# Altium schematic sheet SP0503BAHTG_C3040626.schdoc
size 127 x 101 mm
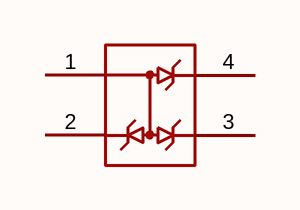
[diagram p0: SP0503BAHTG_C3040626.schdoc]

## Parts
D?  sp0503bahtg_c3040626  [SOT-143-4_L2.9-W1.3-P1.92-LS2.4-BL]  (value not drawn)

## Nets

Not connected (* = marked no-connect by the designer): D? 1 2 3 4

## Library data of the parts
D? = sp0503bahtg_c3040626: 极性:单向;反向截止电压(Vrwm):5.5V;钳位电压:14V;峰值脉冲电流(Ipp):10A@8/20us;峰值脉冲功率(Ppp):150W@8/20us;击穿电压(VBR):6V;; Manufacturer: TECH PUBLIC(台舟); AddInBom: yes; ModelId: 2837e3608ba24a5fbaabe401bacde791; ModelTransform: 114.173,93.3069,0,0,0,0,-0.003,0,0; Polarity: 单向; Reverse Stand-Off Voltage (Vrwm): 5.5V; Clamping Voltage: 14V; Voltage - Breakdown: 6V; Reverse Leakage Current (Ir): 80nA; Number of Channels: 三路; level of protection: IEC 61000-4-2；IEC 61000-4-4；IEC 61000-4-5; Type: ESD; Junction Capacitance: 60pF；30pF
